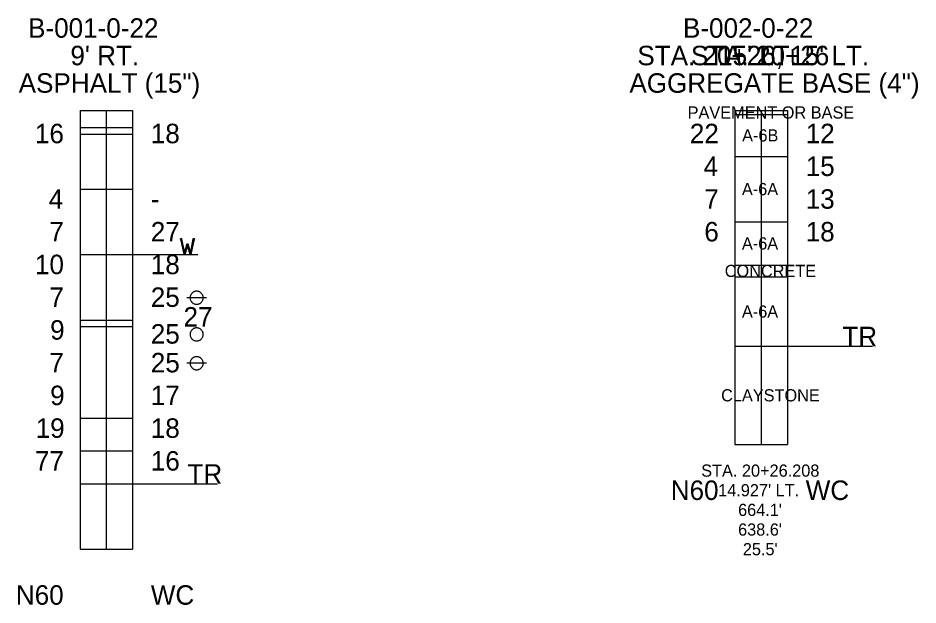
# Model space of a CAD drawing. Extents: x 2284974 to 2285042.7, y 587073.4 to 587118.2.
import ezdxf

# ---------------------------------------------------------------- set-up
doc = ezdxf.new("R2010")
doc.units = 0
for name, color, linetype in [('_CIVIL_CONSTRUCTION', 7, 'Continuous'), ('DR_X_Ditch', 7, 'Continuous'), ('DT_X_Break_Line', 7, 'Continuous'), ('DT_X_Contour_Major', 7, 'Continuous'), ('DT_X_Contour_Text', 7, 'Continuous'), ('DT_X_Island', 7, 'Continuous'), ('DT_X_Spot_Elev', 7, 'Continuous'), ('DT_X_Terrain_Boundary', 7, 'Continuous'), ('DT_X_Void', 7, 'Continuous'), ('PF_X_Ground_Line', 7, 'Continuous'), ('SV_X_Break_Lines', 7, 'Continuous'), ('SV_X_Toe_of_Slope', 7, 'Continuous')]:
    doc.layers.add(name, color=color, linetype=linetype)

msp = doc.modelspace()

# ---------------------------------------------------------------- linework, layer by layer
at = {"layer": 'DT_X_Contour_Major'}
for p, q in [((2285032.742, 587093.128), (2285039.242, 587093.128)), ((2284982.742, 587082.628), (2284989.242, 587082.628))]:
    msp.add_line(p, q, dxfattribs=at)
at = {"layer": 'DT_X_Contour_Text'}
for p, q in [((2284978.742, 587111.128), (2284982.742, 587111.128)), ((2284978.742, 587111.128), (2284978.742, 587077.628)), ((2284982.742, 587111.128), (2284982.742, 587077.628)), ((2285028.742, 587111.128), (2285032.742, 587111.128)), ((2285028.742, 587111.128), (2285028.742, 587085.628)), ((2285028.742, 587110.828), (2285032.742, 587110.828)), ((2285032.742, 587111.128), (2285032.742, 587085.628)), ((2284978.742, 587109.828), (2284982.742, 587109.828)), ((2284978.742, 587109.328), (2284982.742, 587109.328)), ((2285028.742, 587107.628), (2285032.742, 587107.628)), ((2284978.742, 587105.128), (2284982.742, 587105.128)), ((2285028.742, 587102.628), (2285032.742, 587102.628)), ((2284978.742, 587100.128), (2284982.742, 587100.128)), ((2285028.742, 587099.328), (2285032.742, 587099.328)), ((2285028.742, 587098.428), (2285032.742, 587098.428)), ((2284978.742, 587095.128), (2284982.742, 587095.128)), ((2284978.742, 587094.628), (2284982.742, 587094.628)), ((2285028.742, 587093.128), (2285032.742, 587093.128)), ((2284978.742, 587087.628), (2284982.742, 587087.628)), ((2285028.742, 587085.628), (2285032.742, 587085.628)), ((2284978.742, 587085.128), (2284982.742, 587085.128)), ((2284978.742, 587082.628), (2284982.742, 587082.628)), ((2284978.742, 587077.628), (2284982.742, 587077.628))]:
    msp.add_line(p, q, dxfattribs=at)
at = {"layer": 'DT_X_Island'}
for p, q in [((2284980.742, 587111.128), (2284980.742, 587077.628)), ((2285030.742, 587111.128), (2285030.742, 587085.628))]:
    msp.add_line(p, q, dxfattribs=at)
at = {"layer": 'DT_X_Spot_Elev'}
for p, q in [((2284982.742, 587100.128), (2284987.742, 587100.128)), ((2284988.392, 587096.828), (2284986.892, 587096.828)), ((2284988.392, 587091.828), (2284986.892, 587091.828))]:
    msp.add_line(p, q, dxfattribs=at)
for points in [[(2284986.417, 587101.328), (2284986.652, 587100.128), (2284986.715, 587100.341)], [(2284986.417, 587101.328), (2284986.652, 587100.128), (2284986.715, 587100.341), (2284986.417, 587101.328)], [(2284986.417, 587101.328), (2284986.715, 587100.341), (2284986.522, 587101.328)], [(2284986.417, 587101.328), (2284986.715, 587100.341), (2284986.522, 587101.328), (2284986.417, 587101.328)], [(2284987.467, 587101.328), (2284987.362, 587101.328), (2284987.168, 587100.341)], [(2284987.467, 587101.328), (2284987.362, 587101.328), (2284987.168, 587100.341), (2284987.467, 587101.328)], [(2284987.231, 587100.128), (2284987.467, 587101.328), (2284987.168, 587100.341)], [(2284987.231, 587100.128), (2284987.467, 587101.328), (2284987.168, 587100.341), (2284987.231, 587100.128)], [(2284986.652, 587100.128), (2284986.757, 587100.128), (2284986.942, 587100.75)], [(2284986.652, 587100.128), (2284986.757, 587100.128), (2284986.942, 587100.75), (2284986.652, 587100.128)], [(2284986.652, 587100.128), (2284986.942, 587100.75), (2284986.715, 587100.341)], [(2284986.652, 587100.128), (2284986.942, 587100.75), (2284986.715, 587100.341), (2284986.652, 587100.128)], [(2284986.942, 587100.75), (2284986.889, 587100.927), (2284986.715, 587100.341)], [(2284986.942, 587100.75), (2284986.889, 587100.927), (2284986.715, 587100.341), (2284986.942, 587100.75)], [(2284987.168, 587100.341), (2284986.994, 587100.927), (2284986.889, 587100.927)], [(2284987.168, 587100.341), (2284986.994, 587100.927), (2284986.889, 587100.927), (2284987.168, 587100.341)], [(2284986.942, 587100.75), (2284987.168, 587100.341), (2284986.889, 587100.927)], [(2284986.942, 587100.75), (2284987.168, 587100.341), (2284986.889, 587100.927), (2284986.942, 587100.75)], [(2284986.942, 587100.75), (2284987.126, 587100.128), (2284987.231, 587100.128)], [(2284986.942, 587100.75), (2284987.126, 587100.128), (2284987.231, 587100.128), (2284986.942, 587100.75)], [(2284986.942, 587100.75), (2284987.231, 587100.128), (2284987.168, 587100.341)], [(2284986.942, 587100.75), (2284987.231, 587100.128), (2284987.168, 587100.341), (2284986.942, 587100.75)]]:
    msp.add_lwpolyline(points, close=True, dxfattribs=at)
for points in [[(2284987.642, 587096.328), (2284987.681, 587096.329), (2284987.72, 587096.334), (2284987.759, 587096.342), (2284987.797, 587096.352), (2284987.833, 587096.366), (2284987.869, 587096.382), (2284987.903, 587096.401), (2284987.936, 587096.423), (2284987.967, 587096.448), (2284987.996, 587096.474), (2284988.022, 587096.503), (2284988.047, 587096.534), (2284988.068, 587096.566), (2284988.087, 587096.601), (2284988.104, 587096.636), (2284988.118, 587096.673), (2284988.128, 587096.711), (2284988.136, 587096.75), (2284988.14, 587096.788), (2284988.142, 587096.828), (2284988.14, 587096.867), (2284988.136, 587096.906), (2284988.128, 587096.944), (2284988.118, 587096.982), (2284988.104, 587097.019), (2284988.087, 587097.055), (2284988.068, 587097.089), (2284988.047, 587097.122), (2284988.022, 587097.152), (2284987.996, 587097.181), (2284987.967, 587097.208), (2284987.936, 587097.232), (2284987.903, 587097.254), (2284987.869, 587097.273), (2284987.833, 587097.29), (2284987.797, 587097.303), (2284987.759, 587097.314), (2284987.72, 587097.322), (2284987.681, 587097.326), (2284987.642, 587097.328), (2284987.603, 587097.326), (2284987.564, 587097.322), (2284987.525, 587097.314), (2284987.487, 587097.303), (2284987.451, 587097.29), (2284987.415, 587097.273), (2284987.381, 587097.254), (2284987.348, 587097.232), (2284987.317, 587097.208), (2284987.288, 587097.181), (2284987.262, 587097.152), (2284987.237, 587097.122), (2284987.216, 587097.089), (2284987.196, 587097.055), (2284987.18, 587097.019), (2284987.166, 587096.982), (2284987.156, 587096.944), (2284987.148, 587096.906), (2284987.144, 587096.867), (2284987.142, 587096.828), (2284987.144, 587096.788), (2284987.148, 587096.75), (2284987.156, 587096.711), (2284987.166, 587096.673), (2284987.18, 587096.636), (2284987.196, 587096.601), (2284987.216, 587096.566), (2284987.237, 587096.534), (2284987.262, 587096.503), (2284987.288, 587096.474), (2284987.317, 587096.448), (2284987.348, 587096.423), (2284987.381, 587096.401), (2284987.415, 587096.382), (2284987.451, 587096.366), (2284987.487, 587096.352), (2284987.525, 587096.342), (2284987.564, 587096.334), (2284987.603, 587096.329), (2284987.642, 587096.328)], [(2284987.642, 587093.526), (2284987.681, 587093.528), (2284987.72, 587093.532), (2284987.759, 587093.54), (2284987.797, 587093.551), (2284987.833, 587093.564), (2284987.869, 587093.581), (2284987.903, 587093.6), (2284987.936, 587093.622), (2284987.967, 587093.646), (2284987.996, 587093.673), (2284988.022, 587093.701), (2284988.047, 587093.732), (2284988.068, 587093.765), (2284988.087, 587093.799), (2284988.104, 587093.835), (2284988.118, 587093.872), (2284988.128, 587093.909), (2284988.136, 587093.948), (2284988.14, 587093.987), (2284988.142, 587094.026), (2284988.14, 587094.065), (2284988.136, 587094.104), (2284988.128, 587094.143), (2284988.118, 587094.181), (2284988.104, 587094.217), (2284988.087, 587094.253), (2284988.068, 587094.287), (2284988.047, 587094.32), (2284988.022, 587094.351), (2284987.996, 587094.38), (2284987.967, 587094.406), (2284987.936, 587094.431), (2284987.903, 587094.452), (2284987.869, 587094.472), (2284987.833, 587094.488), (2284987.797, 587094.502), (2284987.759, 587094.512), (2284987.72, 587094.52), (2284987.681, 587094.525), (2284987.642, 587094.526), (2284987.603, 587094.525), (2284987.564, 587094.52), (2284987.525, 587094.512), (2284987.487, 587094.502), (2284987.451, 587094.488), (2284987.415, 587094.472), (2284987.381, 587094.452), (2284987.348, 587094.431), (2284987.317, 587094.406), (2284987.288, 587094.38), (2284987.262, 587094.351), (2284987.237, 587094.32), (2284987.216, 587094.287), (2284987.196, 587094.253), (2284987.18, 587094.217), (2284987.166, 587094.181), (2284987.156, 587094.143), (2284987.148, 587094.104), (2284987.144, 587094.065), (2284987.142, 587094.026), (2284987.144, 587093.987), (2284987.148, 587093.948), (2284987.156, 587093.909), (2284987.166, 587093.872), (2284987.18, 587093.835), (2284987.196, 587093.799), (2284987.216, 587093.765), (2284987.237, 587093.732), (2284987.262, 587093.701), (2284987.288, 587093.673), (2284987.317, 587093.646), (2284987.348, 587093.622), (2284987.381, 587093.6), (2284987.415, 587093.581), (2284987.451, 587093.564), (2284987.487, 587093.551), (2284987.525, 587093.54), (2284987.564, 587093.532), (2284987.603, 587093.528), (2284987.642, 587093.526)], [(2284987.642, 587091.328), (2284987.681, 587091.329), (2284987.72, 587091.334), (2284987.759, 587091.342), (2284987.797, 587091.352), (2284987.833, 587091.366), (2284987.869, 587091.382), (2284987.903, 587091.401), (2284987.936, 587091.423), (2284987.967, 587091.448), (2284987.996, 587091.474), (2284988.022, 587091.503), (2284988.047, 587091.534), (2284988.068, 587091.566), (2284988.087, 587091.601), (2284988.104, 587091.636), (2284988.118, 587091.673), (2284988.128, 587091.711), (2284988.136, 587091.75), (2284988.14, 587091.788), (2284988.142, 587091.828), (2284988.14, 587091.867), (2284988.136, 587091.906), (2284988.128, 587091.944), (2284988.118, 587091.982), (2284988.104, 587092.019), (2284988.087, 587092.055), (2284988.068, 587092.089), (2284988.047, 587092.122), (2284988.022, 587092.152), (2284987.996, 587092.181), (2284987.967, 587092.208), (2284987.936, 587092.232), (2284987.903, 587092.254), (2284987.869, 587092.273), (2284987.833, 587092.29), (2284987.797, 587092.303), (2284987.759, 587092.314), (2284987.72, 587092.322), (2284987.681, 587092.326), (2284987.642, 587092.328), (2284987.603, 587092.326), (2284987.564, 587092.322), (2284987.525, 587092.314), (2284987.487, 587092.303), (2284987.451, 587092.29), (2284987.415, 587092.273), (2284987.381, 587092.254), (2284987.348, 587092.232), (2284987.317, 587092.208), (2284987.288, 587092.181), (2284987.262, 587092.152), (2284987.237, 587092.122), (2284987.216, 587092.089), (2284987.196, 587092.055), (2284987.18, 587092.019), (2284987.166, 587091.982), (2284987.156, 587091.944), (2284987.148, 587091.906), (2284987.144, 587091.867), (2284987.142, 587091.828), (2284987.144, 587091.788), (2284987.148, 587091.75), (2284987.156, 587091.711), (2284987.166, 587091.673), (2284987.18, 587091.636), (2284987.196, 587091.601), (2284987.216, 587091.566), (2284987.237, 587091.534), (2284987.262, 587091.503), (2284987.288, 587091.474), (2284987.317, 587091.448), (2284987.348, 587091.423), (2284987.381, 587091.401), (2284987.415, 587091.382), (2284987.451, 587091.366), (2284987.487, 587091.352), (2284987.525, 587091.342), (2284987.564, 587091.334), (2284987.603, 587091.329), (2284987.642, 587091.328)]]:
    msp.add_lwpolyline(points, dxfattribs=at)

# ---------------------------------------------------------------- texts
at = {"layer": '_CIVIL_CONSTRUCTION'}
for s, p in [("9' RT.", (2284978.006, 587114.584)), ("15' LT.", (2285027.454, 587114.584))]:
    msp.add_text(s, height=1.488, dxfattribs=at).set_placement(p)
at = {"layer": 'DR_X_Ditch'}
msp.add_text('STA. 20+26', height=1.488, dxfattribs=at).set_placement((2285025.381, 587114.584))
at = {"layer": 'DT_X_Break_Line'}
for s, p in [('16', (2284975.297, 587108.628)), ('22', (2285025.297, 587108.628)), ('4', (2285026.347, 587106.128)), ('4', (2284976.347, 587103.628)), ('7', (2285026.402, 587103.628)), ('7', (2284976.402, 587101.128)), ('6', (2285026.402, 587101.128)), ('10', (2284975.297, 587098.628)), ('7', (2284976.402, 587096.128)), ('9', (2284976.458, 587093.628)), ('7', (2284976.402, 587091.128)), ('9', (2284976.458, 587088.628)), ('19', (2284975.352, 587086.128)), ('77', (2284975.297, 587083.628))]:
    msp.add_text(s, height=1.488, dxfattribs=at).set_placement(p)
at = {"layer": 'DT_X_Contour_Major'}
for s, p in [('B-001-0-22', (2284974.773, 587116.684)), ('B-002-0-22', (2285024.773, 587116.684)), ('ASPHALT (15")', (2284974.054, 587112.484)), ('AGGREGATE BASE (4")', (2285020.683, 587112.484))]:
    msp.add_text(s, height=1.488, dxfattribs=at).set_placement(p)
at = {"layer": 'DT_X_Terrain_Boundary'}
for s, p in [('N60', (2285023.84, 587081.384)), ('WC', (2285034.144, 587081.384)), ('N60', (2284973.84, 587073.384)), ('WC', (2284984.144, 587073.384))]:
    msp.add_text(s, height=1.488, dxfattribs=at).set_placement(p)
at = {"layer": 'DT_X_Void'}
for s, p in [('18', (2284984.142, 587108.628)), ('12', (2285034.142, 587108.628)), ('15', (2285034.142, 587106.128)), ('13', (2285034.142, 587103.628)), ('-', (2284984.142, 587103.628)), ('27', (2284984.142, 587101.128)), ('18', (2285034.142, 587101.128)), ('18', (2284984.142, 587098.628)), ('25', (2284984.142, 587096.128)), ('27', (2284986.642, 587094.628)), ('25', (2284984.142, 587093.326)), ('TR', (2285036.942, 587093.128)), ('25', (2284984.142, 587091.128)), ('17', (2284984.142, 587088.628)), ('18', (2284984.142, 587086.128)), ('16', (2284984.142, 587083.628)), ('TR', (2284986.942, 587082.628))]:
    msp.add_text(s, height=1.488, dxfattribs=at).set_placement(p)
at = {"layer": 'PF_X_Ground_Line'}
for s, p in [('PAVEMENT OR BASE', (2285025.129, 587110.513)), ('A-6B', (2285029.291, 587108.763)), ('A-6A', (2285029.274, 587104.663)), ('A-6A', (2285029.274, 587100.513)), ('CONCRETE', (2285027.961, 587098.413)), ('A-6A', (2285029.274, 587095.313)), ('CLAYSTONE', (2285027.685, 587088.913))]:
    msp.add_text(s, height=0.93, dxfattribs=at).set_placement(p)
at = {"layer": 'SV_X_Break_Lines'}
for s, p in [('STA. 20+26.208', (2285026.165, 587083.163)), ("14.927' LT.", (2285027.46, 587081.663)), ("664.1'", (2285028.98, 587080.163)), ("638.6'", (2285028.98, 587078.663)), ("25.5'", (2285029.343, 587077.163))]:
    msp.add_text(s, height=0.93, dxfattribs=at).set_placement(p)
at = {"layer": 'SV_X_Toe_of_Slope'}
msp.add_text("STA. 20+26, 15' LT.", height=1.488, dxfattribs=at).set_placement((2285021.291, 587114.584))

doc.saveas('drawing.dxf')
